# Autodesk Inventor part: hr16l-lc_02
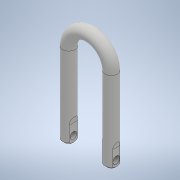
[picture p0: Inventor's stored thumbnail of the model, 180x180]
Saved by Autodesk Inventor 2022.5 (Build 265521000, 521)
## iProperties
Part Number: hr16l-lc_02
Material: 一般
Document SubType Name: Modeling
Designer: ImaoCorp
Density: 1 g/cm^3
Appearance: 既定
Author: ImaoCorp
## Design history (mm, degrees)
feature "hr16l-lc_02"
node "ソリッド1"
